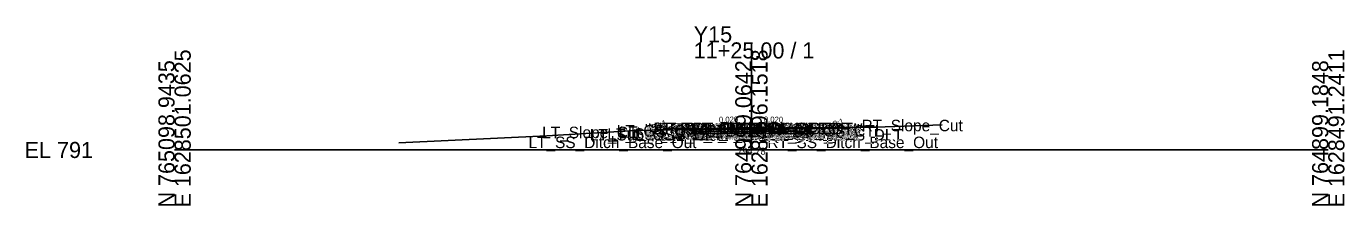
# Model space of a CAD drawing. Extents: x -26 to 203, y -10 to 2522.
# Drawn here: x -25.7 to 202.8, y 2490.3 to 2521.5 of the extents above; entities that cross this region are included whole.
import ezdxf

# ---------------------------------------------------------------- set-up
doc = ezdxf.new("R2010")
doc.units = 0
for name, color, linetype in [('Default', 7, 'Continuous'), ('Exist Cross Section Cell', 7, 'Continuous'), ('Exist XS Center Line Elevation Label', 7, 'Continuous'), ('Exist XS Ground Line', 7, 'Continuous'), ('Prop CMT Concrete Structures', 7, 'Continuous'), ('Prop CMT Pvmt Course 1', 7, 'Continuous'), ('Prop CMT Pvmt Course 2', 7, 'Continuous'), ('Prop CMT Pvmt Course 3', 7, 'Continuous'), ('Prop CMT Pvmt Surface', 7, 'Continuous'), ('Prop CMT Pvmt Surface Shoulder', 7, 'Continuous'), ('Prop CMT Pvmt Wedge Surface 2', 7, 'Continuous'), ('Prop CMT Pvmt Wedge Surface 3', 7, 'Continuous'), ('Prop CMT Shld Paved Course 1', 7, 'Continuous'), ('Prop CMT Shld Paved Course 2', 7, 'Continuous'), ('Prop CMT Shld Paved Course 3', 7, 'Continuous'), ('Prop CMT Slope Grass', 7, 'Continuous'), ('Prop CMT Subgrade Earthwork', 7, 'Continuous'), ('Prop XS SE Text', 7, 'Continuous'), ('Prop XS Side Slope Text', 7, 'Continuous'), ('Scratch_Level_0', 7, 'Continuous')]:
    doc.layers.add(name, color=color, linetype=linetype)

msp = doc.modelspace()

# ---------------------------------------------------------------- linework, layer by layer
at = {"layer": 'Exist Cross Section Cell'}
for p, q in [((100, 2500), (100, 2518.71)), ((0, 2500), (100, 2500)), ((100, 2500), (200, 2500))]:
    msp.add_line(p, q, dxfattribs=at)
at = {"layer": 'Exist XS Ground Line'}
msp.add_lwpolyline([(38.87, 2501.25), (64.52, 2502.46), (79.06, 2503.35), (82.77, 2503.44), (91.06, 2503.56), (94.01, 2503.7), (97.11, 2503.74), (100, 2503.78), (106.19, 2503.86), (115.96, 2503.85), (116.93, 2503.84), (118.04, 2503.88), (119.47, 2503.94), (121.57, 2503.95), (133.09, 2504.38)], dxfattribs=at)
at = {"layer": 'Prop CMT Concrete Structures'}
for points in [[(90.27, 2503.72), (90.28, 2503.14), (92.28, 2503.14)], [(92.28, 2503.72), (91.28, 2503.64), (90.27, 2503.72)], [(92.28, 2503.14), (92.28, 2503.72)], [(109.73, 2503.72), (109.73, 2503.14), (107.73, 2503.14)], [(107.73, 2503.72), (108.73, 2503.64), (109.73, 2503.72)], [(107.73, 2503.14), (107.73, 2503.72)]]:
    msp.add_lwpolyline(points, dxfattribs=at)
at = {"layer": 'Prop CMT Pvmt Course 1'}
for points in [[(100, 2503.88), (92.28, 2503.72)], [(92.28, 2503.72), (92.28, 2503.47)], [(92.28, 2503.47), (100, 2503.63)], [(100, 2503.88), (94.01, 2503.76)], [(100, 2503.75), (100, 2503.88)], [(100, 2503.63), (100, 2503.88)], [(100, 2503.88), (106.19, 2503.75)], [(100, 2503.75), (100, 2503.88)], [(100, 2503.88), (107.73, 2503.72)], [(100, 2503.63), (100, 2503.88)], [(107.73, 2503.47), (100, 2503.63)], [(107.73, 2503.72), (107.73, 2503.47)]]:
    msp.add_lwpolyline(points, dxfattribs=at)
at = {"layer": 'Prop CMT Pvmt Course 2'}
for points in [[(100, 2503.63), (92.28, 2503.47)], [(92.28, 2503.47), (92.28, 2503.14)], [(92.28, 2503.14), (100, 2503.29)], [(100, 2503.29), (100, 2503.63)], [(100, 2503.29), (100, 2503.63)], [(100, 2503.63), (107.73, 2503.47)], [(107.73, 2503.14), (100, 2503.29)], [(107.73, 2503.47), (107.73, 2503.14)]]:
    msp.add_lwpolyline(points, dxfattribs=at)
at = {"layer": 'Prop CMT Pvmt Course 3'}
msp.add_line((109.73, 2503.14), (110.23, 2503.14), dxfattribs=at)
for points in [[(100, 2503.29), (92.28, 2503.14)], [(92.28, 2503.14), (92.28, 2502.8)], [(92.28, 2502.8), (100, 2502.96)], [(100, 2502.96), (100, 2503.29)], [(100, 2503.29), (107.73, 2503.14)], [(100, 2502.96), (100, 2503.29)], [(107.73, 2502.8), (100, 2502.96)], [(107.73, 2503.14), (107.73, 2502.8)]]:
    msp.add_lwpolyline(points, dxfattribs=at)
at = {"layer": 'Prop CMT Pvmt Surface'}
for points in [[(100, 2503.88), (92.28, 2503.72)], [(100, 2503.88), (94.01, 2503.76)], [(100, 2503.88), (107.73, 2503.72)], [(100, 2503.88), (106.19, 2503.75)]]:
    msp.add_lwpolyline(points, dxfattribs=at)
at = {"layer": 'Prop CMT Pvmt Surface Shoulder'}
for points in [[(92.28, 2503.72), (92.28, 2503.72)], [(107.73, 2503.72), (107.73, 2503.72)]]:
    msp.add_lwpolyline(points, dxfattribs=at)
at = {"layer": 'Prop CMT Pvmt Wedge Surface 2'}
for points in [[(100, 2503.63), (94.01, 2503.51)], [(100, 2503.63), (100, 2503.88)], [(100, 2503.63), (100, 2503.88)], [(100, 2503.63), (100, 2503.88)], [(100, 2503.63), (100, 2503.88)], [(100, 2503.63), (106.19, 2503.5)]]:
    msp.add_lwpolyline(points, dxfattribs=at)
at = {"layer": 'Prop CMT Pvmt Wedge Surface 3'}
for points in [[(100, 2503.29), (94.01, 2503.17)], [(100, 2503.29), (100, 2503.88)], [(100, 2503.29), (100, 2503.88)], [(100, 2503.29), (100, 2503.88)], [(100, 2503.29), (100, 2503.88)], [(100, 2503.29), (106.19, 2503.17)]]:
    msp.add_lwpolyline(points, dxfattribs=at)
at = {"layer": 'Prop CMT Shld Paved Course 1'}
for points in [[(92.28, 2503.72), (92.28, 2503.72)], [(92.28, 2503.47), (92.28, 2503.72)], [(107.73, 2503.72), (107.73, 2503.72)], [(107.73, 2503.47), (107.73, 2503.72)]]:
    msp.add_lwpolyline(points, dxfattribs=at)
at = {"layer": 'Prop CMT Shld Paved Course 2'}
for p, q in [((90.28, 2503.14), (92.28, 2503.14)), ((109.73, 2503.14), (107.73, 2503.14))]:
    msp.add_line(p, q, dxfattribs=at)
for points in [[(92.28, 2503.14), (92.28, 2503.47)], [(107.73, 2503.14), (107.73, 2503.47)]]:
    msp.add_lwpolyline(points, dxfattribs=at)
at = {"layer": 'Prop CMT Shld Paved Course 3'}
for p, q in [((89.43, 2502.8), (92.28, 2502.8)), ((110.57, 2502.8), (107.73, 2502.8))]:
    msp.add_line(p, q, dxfattribs=at)
for points in [[(92.28, 2503.14), (90.28, 2503.14), (89.78, 2503.14), (89.43, 2502.8)], [(92.28, 2502.8), (92.28, 2503.14)], [(107.73, 2502.8), (107.73, 2503.14)], [(107.73, 2503.14), (110.23, 2503.14), (110.23, 2503.14), (110.57, 2502.8)]]:
    msp.add_lwpolyline(points, dxfattribs=at)
at = {"layer": 'Prop CMT Slope Grass'}
for points in [[(90.27, 2503.72), (85.27, 2503.82), (84.19, 2503.46)], [(109.73, 2503.72), (114.73, 2503.82), (114.82, 2503.85)]]:
    msp.add_lwpolyline(points, dxfattribs=at)
at = {"layer": 'Prop CMT Subgrade Earthwork'}
for p, q in [((89.43, 2502.8), (88.48, 2503.76)), ((92.28, 2502.8), (89.43, 2502.8)), ((107.73, 2502.8), (110.57, 2502.8)), ((110.57, 2502.8), (111.53, 2503.76))]:
    msp.add_line(p, q, dxfattribs=at)
for points in [[(100, 2502.96), (92.28, 2502.8)], [(100, 2502.96), (107.73, 2502.8)]]:
    msp.add_lwpolyline(points, dxfattribs=at)

# ---------------------------------------------------------------- texts
at = {"layer": 'Default'}
msp.add_text('-', height=0.0001, dxfattribs=at).set_placement((0, 2500))
at = {"layer": 'Exist Cross Section Cell'}
for s, p in [('Y15', (90, 2518.71)), ('11+25.00 / 1', (90, 2515.91)), ('EL 791', (-26, 2498.6))]:
    msp.add_text(s, height=2.8, dxfattribs=at).set_placement(p)
for s, p in [('E 1628501.0625', (2.8, 2490)), ('E 1628496.1518', (102.8, 2490)), ('E 1628491.2411', (202.8, 2490)), ('N 765098.9435', (0, 2490)), ('N 764999.0642', (100, 2490)), ('N 764899.1848', (200, 2490))]:
    msp.add_text(s, height=2.8, rotation=90, dxfattribs=at).set_placement(p)
at = {"layer": 'Exist XS Center Line Elevation Label'}
msp.add_text('794.78', height=1.2, dxfattribs=at).set_placement((97.55, 2499.18))
at = {"layer": 'Prop XS SE Text'}
for rotation, p in [(1.1458, (94.37, 2504.76)), (358.8542, (102.14, 2504.83))]:
    msp.add_text('0.020', height=1, rotation=rotation, dxfattribs=at).set_placement(p)
at = {"layer": 'Prop XS Side Slope Text'}
for p in [(83.63, 2503.74), (114.37, 2504.01)]:
    msp.add_text('3:1', height=1, rotation=18.4349, dxfattribs=at).set_placement(p)
at = {"layer": 'Scratch_Level_0'}
for s, p in [('LT_PV1_OEOT', (83.02, 2502.72)), ('LT_PS1_OEOP', (83.08, 2502.72)), ('LT_PV1_OEEOP', (83.89, 2502.76)), ('RT_PV1_PGL_W', (89.84, 2502.75)), ('LT_PV1_PGL_W', (89.89, 2502.75)), ('PV1_PGL', (94.47, 2502.88)), ('RT_PV1_OEEOP', (96.02, 2502.75)), ('RT_PV1_OEOT', (98.42, 2502.72)), ('RT_PS1_OEOP', (98.49, 2502.72)), ('RT_Slope_Cut', (119.1, 2503.25)), ('LT_Slope_Cut', (63.73, 2502.05)), ('LT_Sub_OSS_DLT', (72, 2501.65)), ('LT_Sub_Trench_Out', (75.04, 2501.78)), ('LT_GS_OS_CTL', (76.65, 2502.32)), ('LT_PS3_Shelf_Out', (77.16, 2502.12)), ('LT_PV2_OEEOP_W', (81.43, 2502.51)), ('LT_PV3_OEEOP_W', (81.43, 2502.17)), ('LT_PS3_OEOP', (81.92, 2502.13)), ('LT_PV1_OEEOP_W', (82, 2502.63)), ('LT_PS2_OEOP', (82.26, 2502.47)), ('LT_Sub_OEOT', (82.35, 2501.8)), ('LT_PV2_OEOT', (82.45, 2502.47)), ('LT_PV3_OEOT', (82.45, 2502.14)), ('RT_Sub_Trench_Out', (93.32, 2501.78)), ('RT_PV2_OEEOP_W', (93.56, 2502.5)), ('RT_PV3_OEEOP_W', (93.56, 2502.17)), ('Sub_PGL', (93.81, 2501.96)), ('PV2_PGL', (93.91, 2502.63)), ('PV3_PGL', (93.91, 2502.29)), ('RT_PV1_OEEOP_W', (94.13, 2502.63)), ('RT_PS3_Shelf_Out', (94.76, 2502.12)), ('RT_Sub_OEOT', (97.76, 2501.8)), ('RT_PV2_OEOT', (97.86, 2502.47)), ('RT_PV3_OEOT', (97.86, 2502.14)), ('RT_PS2_OEOP', (98.18, 2502.47)), ('RT_PS3_OEOP', (98.52, 2502.13)), ('RT_GS_OS_CTL', (102.05, 2502.32)), ('RT_Sub_OSS_DLT', (102.77, 2501.65)), ('LT_SS_Ditch_Base_Out', (61.35, 2500.32)), ('RT_SS_Ditch_Base_Out', (102.76, 2500.32))]:
    msp.add_text(s, height=2, dxfattribs=at).set_placement(p)

doc.saveas('drawing.dxf')
